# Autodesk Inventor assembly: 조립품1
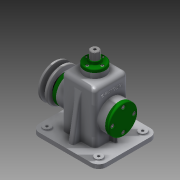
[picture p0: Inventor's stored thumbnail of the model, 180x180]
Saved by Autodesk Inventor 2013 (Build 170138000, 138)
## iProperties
Created: 2016-01
Part Number: 조립품1
Document SubType Name: Assembly
Designer: Administrator
Author: Administrator
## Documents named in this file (19)
- C:\Users\Administrator\Desktop\460127V1010\조립품1.iam
- C:\Users\Administrator\Desktop\460127V1010\1부품.ipt
- C:\Users\Administrator\Desktop\460127V1010\V-벨트풀리.ipt
- C:\Users\Administrator\Desktop\460127V1010\고정핀.ipt
- C:\Users\Administrator\Desktop\460127V1010\뒤커버.ipt
- C:\Users\Administrator\Desktop\460127V1010\링크.ipt
- C:\Users\Administrator\Desktop\460127V1010\멈춤링 6 x 5.ipt
- C:\Users\Administrator\Desktop\460127V1010\멈춤링 15 x 1.ipt
- C:\Users\Administrator\Desktop\460127V1010\베어링 15 x 35 x 11.ipt
- C:\Users\Administrator\Desktop\460127V1010\볼트 M3 x 8.ipt
- C:\Users\Administrator\Desktop\460127V1010\볼트 M4 x 10.ipt
- C:\Users\Administrator\Desktop\460127V1010\볼트 M6 x 12.ipt
- C:\Users\Administrator\Desktop\460127V1010\상부부시.ipt
- C:\Users\Administrator\Desktop\460127V1010\슬라이드바.ipt
- C:\Users\Administrator\Desktop\460127V1010\앞커버.ipt
- C:\Users\Administrator\Desktop\460127V1010\오일실 15 25 7.ipt
- C:\Users\Administrator\Desktop\460127V1010\와셔.ipt
- C:\Users\Administrator\Desktop\460127V1010\키 5 x 5 x 14.ipt
- C:\Users\Administrator\Desktop\460127V1010\편심축.ipt
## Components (16 placed, 6 different names)
1. 1부품:1
2. V-벨트풀리:1 — 각도:2
3. 고정핀:1
4. ISO 4018 M6 x 12:1
5. ISO 4762 M4 x 10:2
6. ISO 4762 M4 x 10:3
7. ISO 4762 M4 x 10:4
8. ISO 4762 M4 x 10:5
9. ISO 4762 M4 x 10:6
10. ISO 4762 M4 x 10:7
11. ISO 4762 M4 x 10:8
12. ISO 4762 M4 x 10:9
13. ISO 4762 M3 x 8:2
14. ISO 4762 M3 x 8:3
15. ISO 4762 M3 x 8:4
16. ISO 4762 M3 x 8:5
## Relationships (1: Angle 1)
- 각도:2 [Angle]: V-벨트풀리:1
